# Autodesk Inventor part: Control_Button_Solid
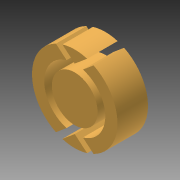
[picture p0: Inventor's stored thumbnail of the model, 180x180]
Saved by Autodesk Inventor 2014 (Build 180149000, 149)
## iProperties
Created: 2008-08
Part Number: Control_Button_Solid
Document SubType Name: Modeling
Designer: PN
Density: 1 g/cm^3
Material: Generic
Appearance: Orange (Pale)
Author: MSD
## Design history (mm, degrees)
sketch "Sketch1"
  geometry: L1 (0, 0)-(0, 25.058); L2 (4.053, 13.401)-(0, 10); L3 (-4.053, 13.401)-(0, 10); L4 (-6.17, 12.567)-(-2.677, 9.635); L5 (2.677, 9.635)-(6.17, 12.567); L6 (0, 0)-(20.924, 0); L7 (-4.053, -13.401)-(0, -10); L8 (-6.17, -12.567)-(-2.677, -9.635); L9 (4.053, -13.401)-(0, -10); L10 (2.677, -9.635)-(6.17, -12.567); C1 r 7.5 at (0, 0); A1 r 10 centre (0, 0) between (0, 10) and (0, 10); A2 r 14 centre (0, 0) between (4.053, 13.401) and (-4.053, 13.401); A3 r 14 centre (0, 0) between (6.17, -12.567) and (6.17, 12.567); A4 r 10 centre (0, 0) between (2.677, -9.635) and (2.677, 9.635); A5 r 10 centre (0, 0) between (-2.677, 9.635) and (-2.677, -9.635); A6 r 10 centre (0, 0) between (0, -10) and (0, -10); A7 r 14 centre (0, 0) between (-6.17, 12.567) and (-6.17, -12.567); A8 r 14 centre (0, 0) between (-4.053, -13.401) and (4.053, -13.401); 1 further point
  constraints: 20 end point, 16 point on circle, 9 centre point, 8 symmetric about line, 4 coincident, 2 parallel, 1 perpendicular, 1 vertical
  dimensions: "d0" = 15 diameter of C1; "d6" = 50 deg angle of L1 L3; "d7" = 50 deg angle of L2 L1; "d8" = 10 distance of L3.end point (0, 0); "d9" = 10 distance of L2.end point (0, 0) (= d8); "d10" = 2 distance between parallel lines of L5 L2; "d11" = 2 distance between parallel lines of L4 L3 (= d10); "d14" = 2.5 radial gap between concentric circles of C1 A5; "d15" = 2.5 radial gap between concentric circles of C1 A1 (= d14); "d16" = 2.5 radial gap between concentric circles of C1 A4 (= d14); "d17" = 4 radial gap between concentric circles of A5 A7; "d18" = 4 radial gap between concentric circles of A8 A6 (= d17); "d19" = 4 radial gap between concentric circles of A3 A4 (= d17)
extrude "Extrusion1" new body sketch "Sketch1" distance "d12" = 10; taper "d13" = 0 deg
body "Solid1"
other parameters: "d1" = 2.5, "d2" = 4
